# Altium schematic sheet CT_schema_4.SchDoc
size 522 x 390 mm
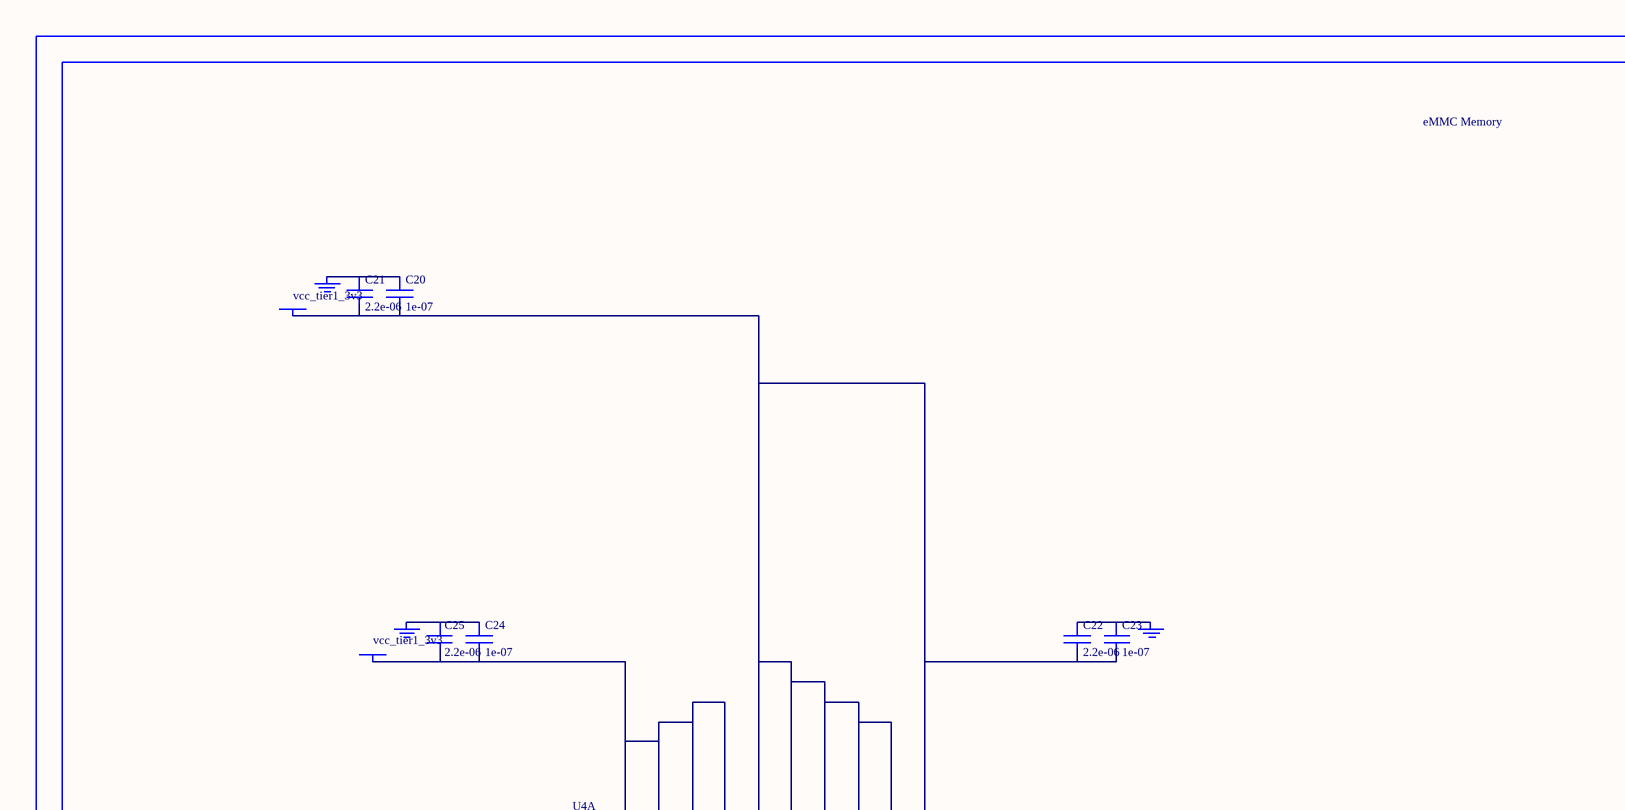
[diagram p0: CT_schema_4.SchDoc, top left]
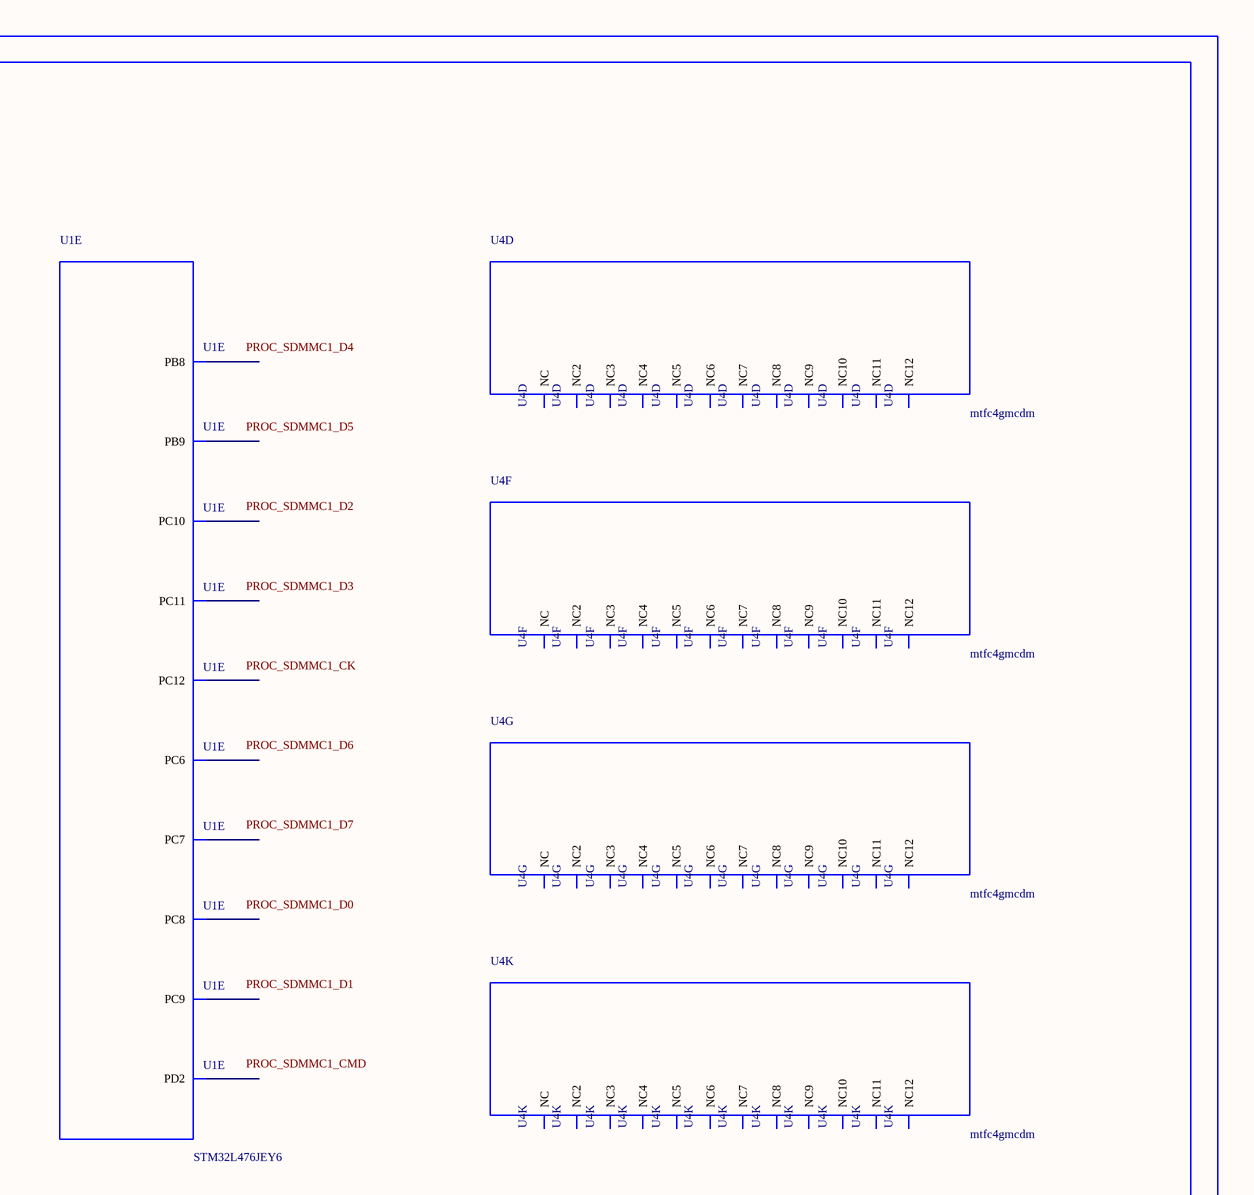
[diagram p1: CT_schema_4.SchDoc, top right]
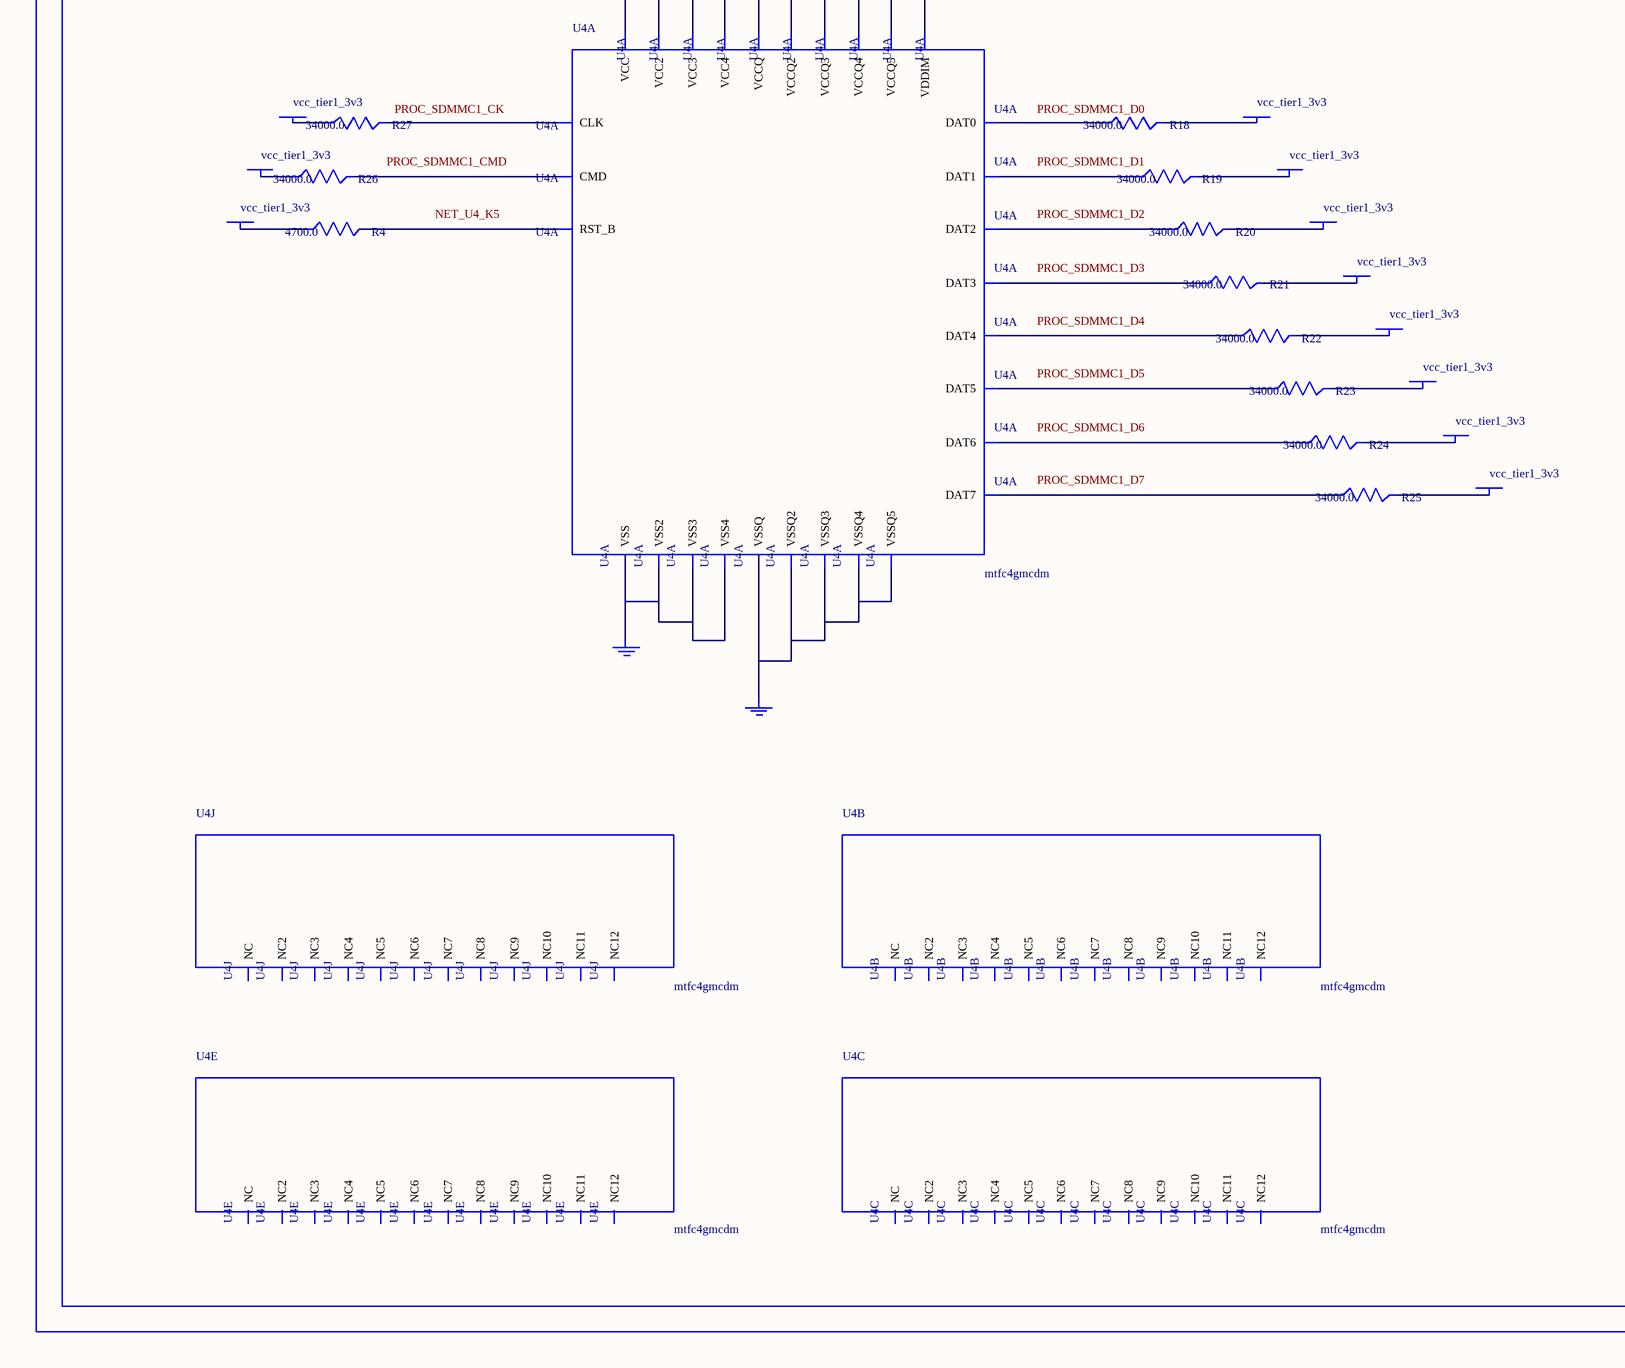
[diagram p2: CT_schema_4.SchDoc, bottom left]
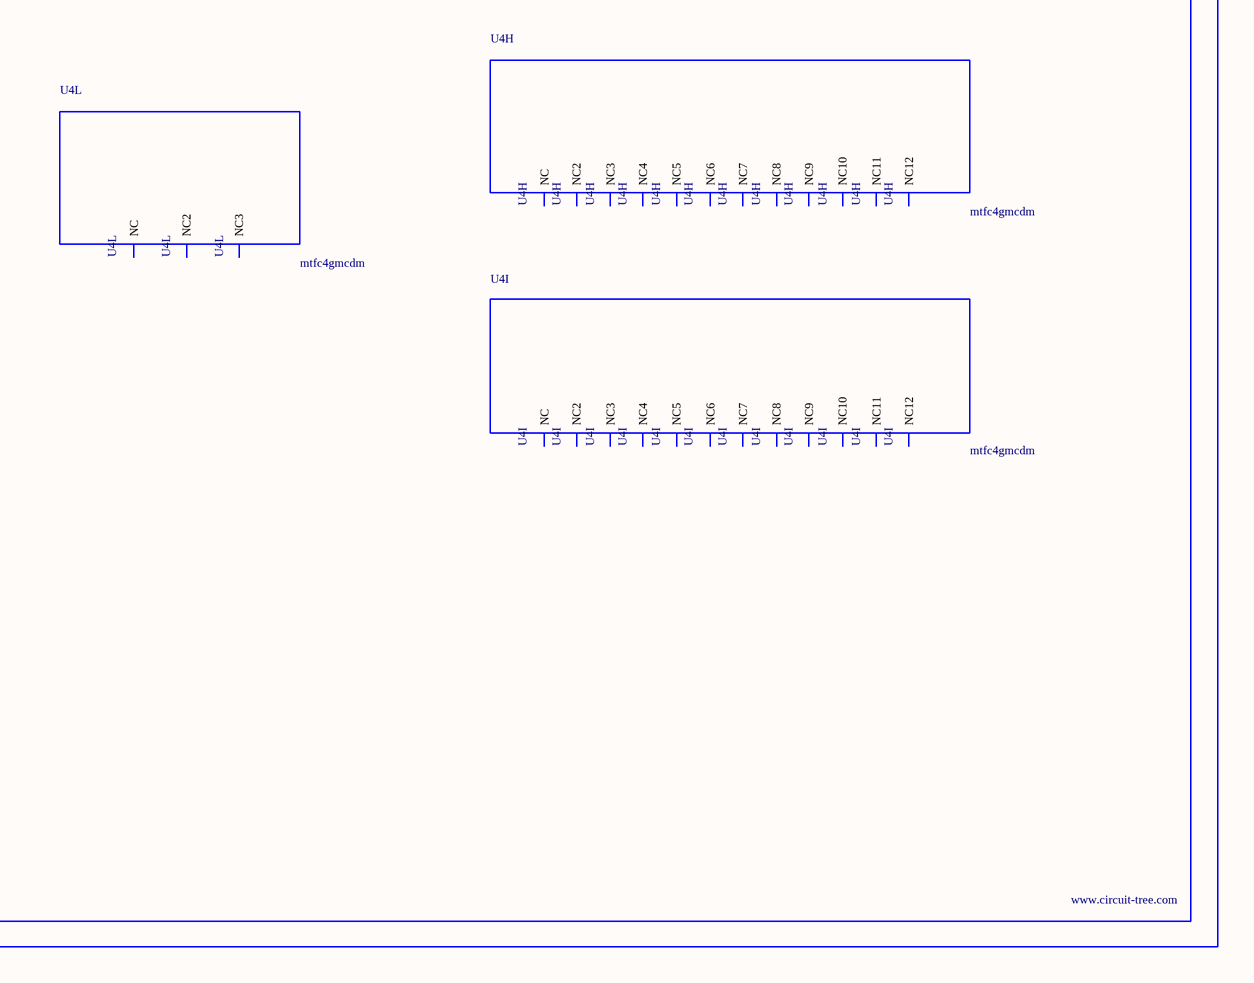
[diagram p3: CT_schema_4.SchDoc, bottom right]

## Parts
BORDER3  (no value)
C20  1e-07  [C0402]
C21  2.2e-06  [C0603]
C22  2.2e-06  [C0603]
C23  1e-07  [C0402]
C24  1e-07  [C0402]
C25  2.2e-06  [C0603]
GND_INSTANCE_3_0  (no value)
GND_INSTANCE_3_1  (no value)
GND_INSTANCE_3_2  (no value)
GND_INSTANCE_3_3  (no value)
GND_INSTANCE_3_4  (no value)
POWER_INSTANCE_3_0  vcc_tier1_3v3
POWER_INSTANCE_3_1  vcc_tier1_3v3
POWER_INSTANCE_3_2  vcc_tier1_3v3
POWER_INSTANCE_3_3  vcc_tier1_3v3
POWER_INSTANCE_3_4  vcc_tier1_3v3
POWER_INSTANCE_3_5  vcc_tier1_3v3
POWER_INSTANCE_3_6  vcc_tier1_3v3
POWER_INSTANCE_3_7  vcc_tier1_3v3
POWER_INSTANCE_3_8  vcc_tier1_3v3
POWER_INSTANCE_3_9  vcc_tier1_3v3
POWER_INSTANCE_3_10  vcc_tier1_3v3
POWER_INSTANCE_3_11  vcc_tier1_3v3
POWER_INSTANCE_3_12  vcc_tier1_3v3
R4  4700.0  [R0603]
R18  34000.0  [R0603]
R19  34000.0  [R0603]
R20  34000.0  [R0603]
R21  34000.0  [R0603]
R22  34000.0  [R0603]
R23  34000.0  [R0603]
R24  34000.0  [R0603]
R25  34000.0  [R0603]
R26  34000.0  [R0603]
R27  34000.0  [R0603]
U1  STM32L476JEY6  [WLCSP72]  (part E of 6)
U4  mtfc4gmcdm  [TFBGA-153]  (parts A,B,C,D,E,F,G,H,I,J,K,L of 12)

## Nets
NetC20_1: C20.1 C21.1 GND_INSTANCE_3_0.0(GND)
NetC20_2: C20.2 C21.2 C22.2 C23.2 POWER_INSTANCE_3_0.0(PWR) U4.C2(VDDIM) U4.C6(VCCQ) U4.M4(VCCQ2) U4.N4(VCCQ3) U4.P3(VCCQ4) U4.P5(VCCQ5)
NetC22_1: C22.1 C23.1 GND_INSTANCE_3_1.0(GND)
NetC24_1: C24.1 C25.1 GND_INSTANCE_3_2.0(GND)
NetC24_2: C24.2 C25.2 POWER_INSTANCE_3_1.0(PWR) U4.E6(VCC) U4.F5(VCC2) U4.J10(VCC3) U4.K9(VCC4)
NetGND_INSTANCE_3_3_0: GND_INSTANCE_3_3.0(GND) U4.E7(VSS) U4.G5(VSS2) U4.H10(VSS3) U4.K8(VSS4)
NetGND_INSTANCE_3_4_0: GND_INSTANCE_3_4.0(GND) U4.C4(VSSQ) U4.N2(VSSQ2) U4.N5(VSSQ3) U4.P4(VSSQ4) U4.P6(VSSQ5)
NetPOWER_INSTANCE_3_2_0: POWER_INSTANCE_3_2.0(PWR) R18.2
NetPOWER_INSTANCE_3_3_0: POWER_INSTANCE_3_3.0(PWR) R19.2
NetPOWER_INSTANCE_3_4_0: POWER_INSTANCE_3_4.0(PWR) R20.2
NetPOWER_INSTANCE_3_5_0: POWER_INSTANCE_3_5.0(PWR) R21.2
NetPOWER_INSTANCE_3_6_0: POWER_INSTANCE_3_6.0(PWR) R22.2
NetPOWER_INSTANCE_3_7_0: POWER_INSTANCE_3_7.0(PWR) R23.2
NetPOWER_INSTANCE_3_8_0: POWER_INSTANCE_3_8.0(PWR) R24.2
NetPOWER_INSTANCE_3_9_0: POWER_INSTANCE_3_9.0(PWR) R25.2
NetPOWER_INSTANCE_3_10_0: POWER_INSTANCE_3_10.0(PWR) R26.1
NetPOWER_INSTANCE_3_11_0: POWER_INSTANCE_3_11.0(PWR) R27.1
NetPOWER_INSTANCE_3_12_0: POWER_INSTANCE_3_12.0(PWR) R4.1
NetR4_2: R4.2 U4.K5(RST_B)
NetR18_1: R18.1 U4.A3(DAT0)
NetR19_1: R19.1 U4.A4(DAT1)
NetR20_1: R20.1 U4.A5(DAT2)
NetR21_1: R21.1 U4.B2(DAT3)
NetR22_1: R22.1 U4.B3(DAT4)
NetR23_1: R23.1 U4.B4(DAT5)
NetR24_1: R24.1 U4.B5(DAT6)
NetR25_1: R25.1 U4.B6(DAT7)
NetR26_2: R26.2 U4.M5(CMD)
NetR27_2: R27.2 U4.M6(CLK)

Not connected (* = marked no-connect by the designer): U1 A3(PD2) B3(PC12) C3(PC11) D3(PC10) E1(PC9) E7(PB8) E8(PB9) F1(PC7) F2(PC8) F3(PC6); U4 A1(NC) A2(NC7) A6(NC8) A7(NC9) A8(NC10) A9(NC11) A10(NC2) A11(NC3) A12(NC4) A13(NC5) A14(NC6) B1(NC12) B7(NC6) B8(NC7) B9(NC8) B10(NC) B11(NC2) B12(NC3) B13(NC4) B14(NC5) C1(NC9) C3(NC10) C5(NC11) C7(NC12) C8(NC6) C9(NC7) C10(NC) C11(NC2) C12(NC3) C13(NC4) C14(NC5) D1(NC8) D2(NC10) D3(NC11) D4(NC12) D12(NC9) D13(NC) D14(NC2) E1(NC3) E2(NC8) E3(NC9) E5(NC10) E8(NC11) E9(NC12) E10(NC4) E12(NC5) E13(NC6) E14(NC7) F1(NC) F2(NC6) F3(NC7) F10(NC2) F12(NC3) F13(NC4) F14(NC5) G1(NC8) G2(NC11) G3(NC12) G10(NC9) G12(NC10) G13(NC) G14(NC2) H1(NC3) H2(NC7) H3(NC8) H5(NC9) H12(NC4) H13(NC5) H14(NC6) J1(NC10) J2(NC11) J3(NC12) J5(NC4) J12(NC) J13(NC2) J14(NC3) K1(NC5) K2(NC9) K3(NC10) K6(NC11) K7(NC12) K10(NC6) K12(NC7) K13(NC8) K14(NC) L1(NC2) L2(NC6) L3(NC7) L12(NC3) L13(NC4) L14(NC5) M1(NC8) M2(NC9) M3(NC10) M7(NC11) M8(NC12) M9(NC6) M10(NC) M11(NC2) M12(NC3) M13(NC4) M14(NC5) N1(NC7) N3(NC8) N6(NC9) N7(NC10) N8(NC11) N9(NC12) N10(NC) N11(NC2) N12(NC3) N13(NC4) N14(NC5) P1(NC6) P2(NC9) P7(NC10) P8(NC11) P9(NC12) P10(NC7) P11(NC8) P12(NC) P13(NC2) P14(NC3)

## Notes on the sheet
- Labels drawn without touching a wire or pin: NET_U4_K5, PROC_SDMMC1_CK, PROC_SDMMC1_CMD, PROC_SDMMC1_D0, PROC_SDMMC1_D1, PROC_SDMMC1_D2, PROC_SDMMC1_D3, PROC_SDMMC1_D4, PROC_SDMMC1_D5, PROC_SDMMC1_D6, PROC_SDMMC1_D7

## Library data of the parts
BORDER3 = BORDER_PAGE3
C20 C23 C24 = C0402C104K3RACTU
C21 C22 C25 = C0603C225K8RACTU
GND_INSTANCE_3_0-GND_INSTANCE_3_4 = GND
POWER_INSTANCE_3_0-POWER_INSTANCE_3_12 = PWR
R4 = RC0603JR-074K7L
R18-R27 = ERA3ARB3402V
